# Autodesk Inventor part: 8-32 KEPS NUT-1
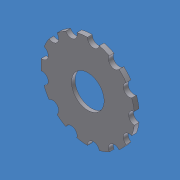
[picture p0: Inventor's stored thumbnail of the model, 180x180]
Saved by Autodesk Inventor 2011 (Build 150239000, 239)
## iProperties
Created: 2007-09
Part Number: 8-32 KEPS NUT-1
Document SubType Name: Modeling
Material: Stainless Steel
Density: 8.08 g/cm^3
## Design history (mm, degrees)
feature "Base1"
body "Solid1"
